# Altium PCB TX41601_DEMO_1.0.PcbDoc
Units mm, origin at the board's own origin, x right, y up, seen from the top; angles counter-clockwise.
Board outline 65 x 65 mm, 4 copper layers (Top Layer, Signal Layer 1, Signal Layer 2, Bottom Layer), stack 0.778 mm thick; 65 components, 52 nets, 196 pads, 383 vias.
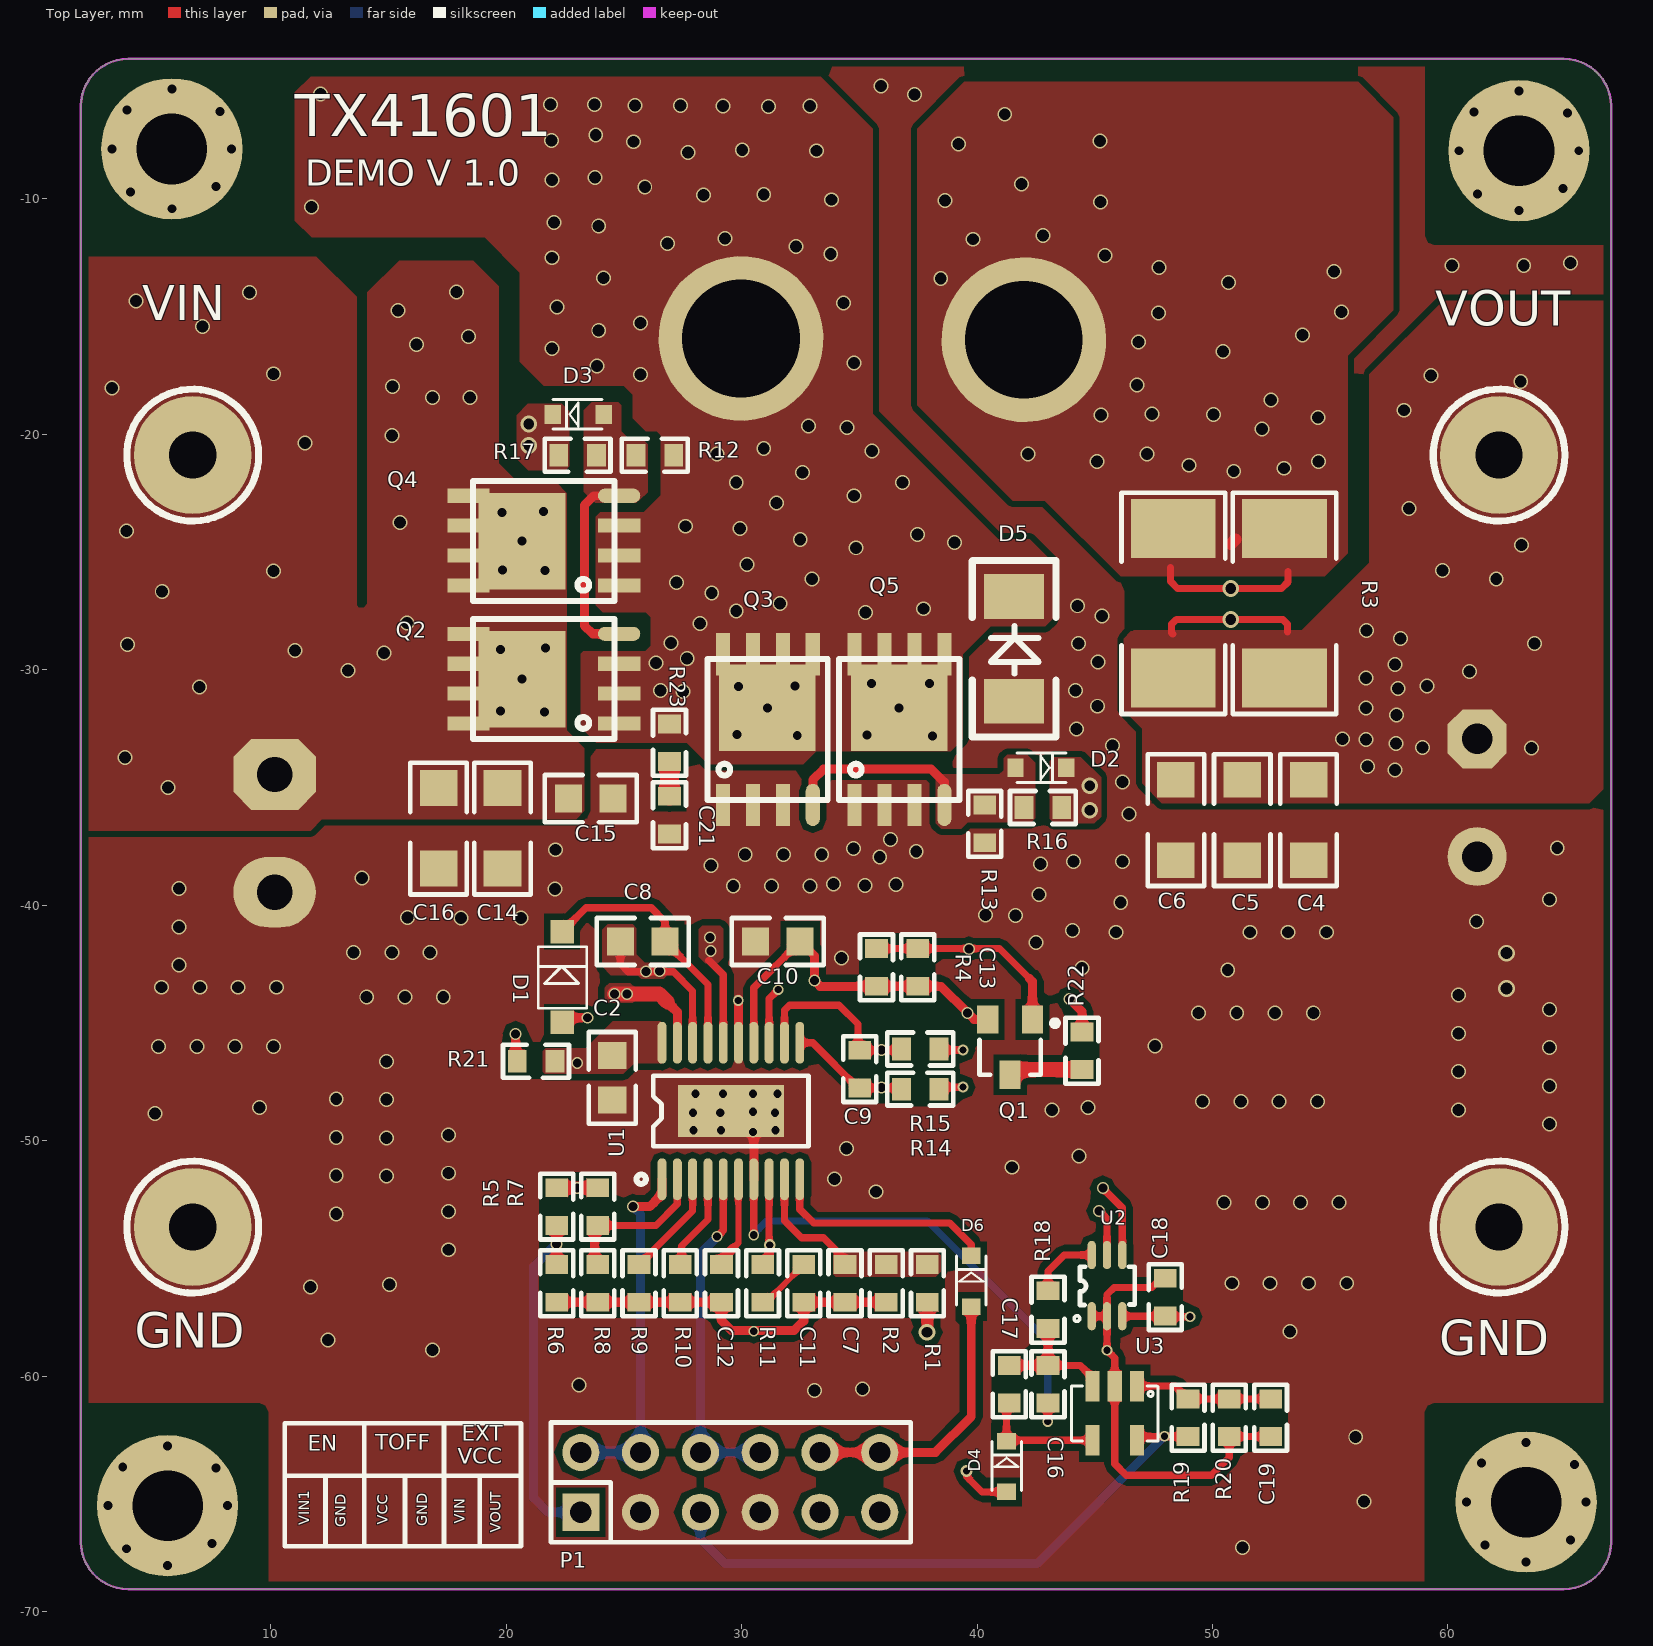
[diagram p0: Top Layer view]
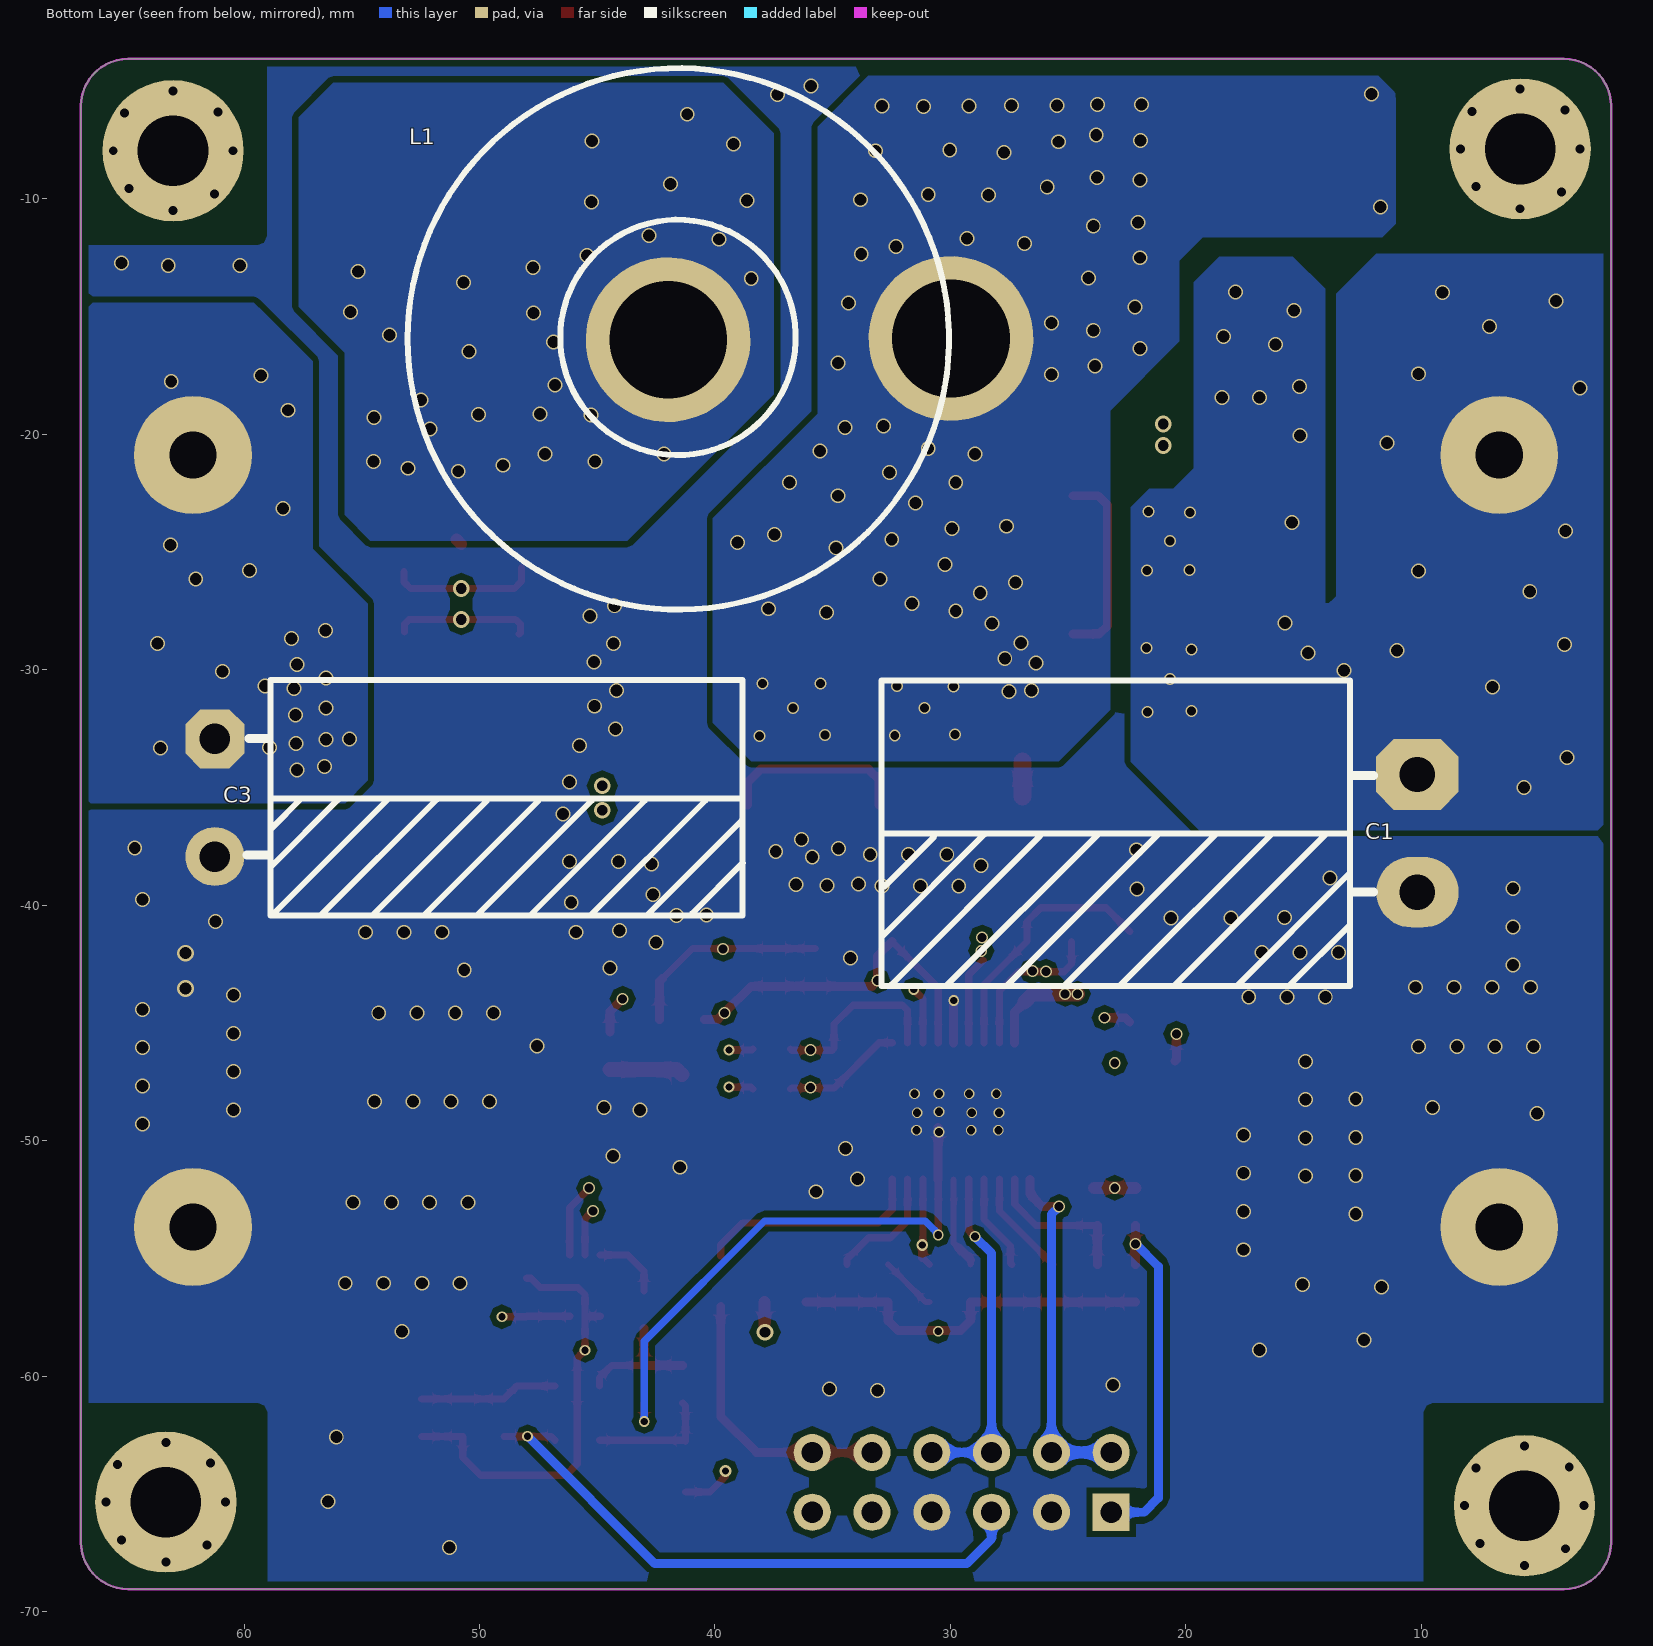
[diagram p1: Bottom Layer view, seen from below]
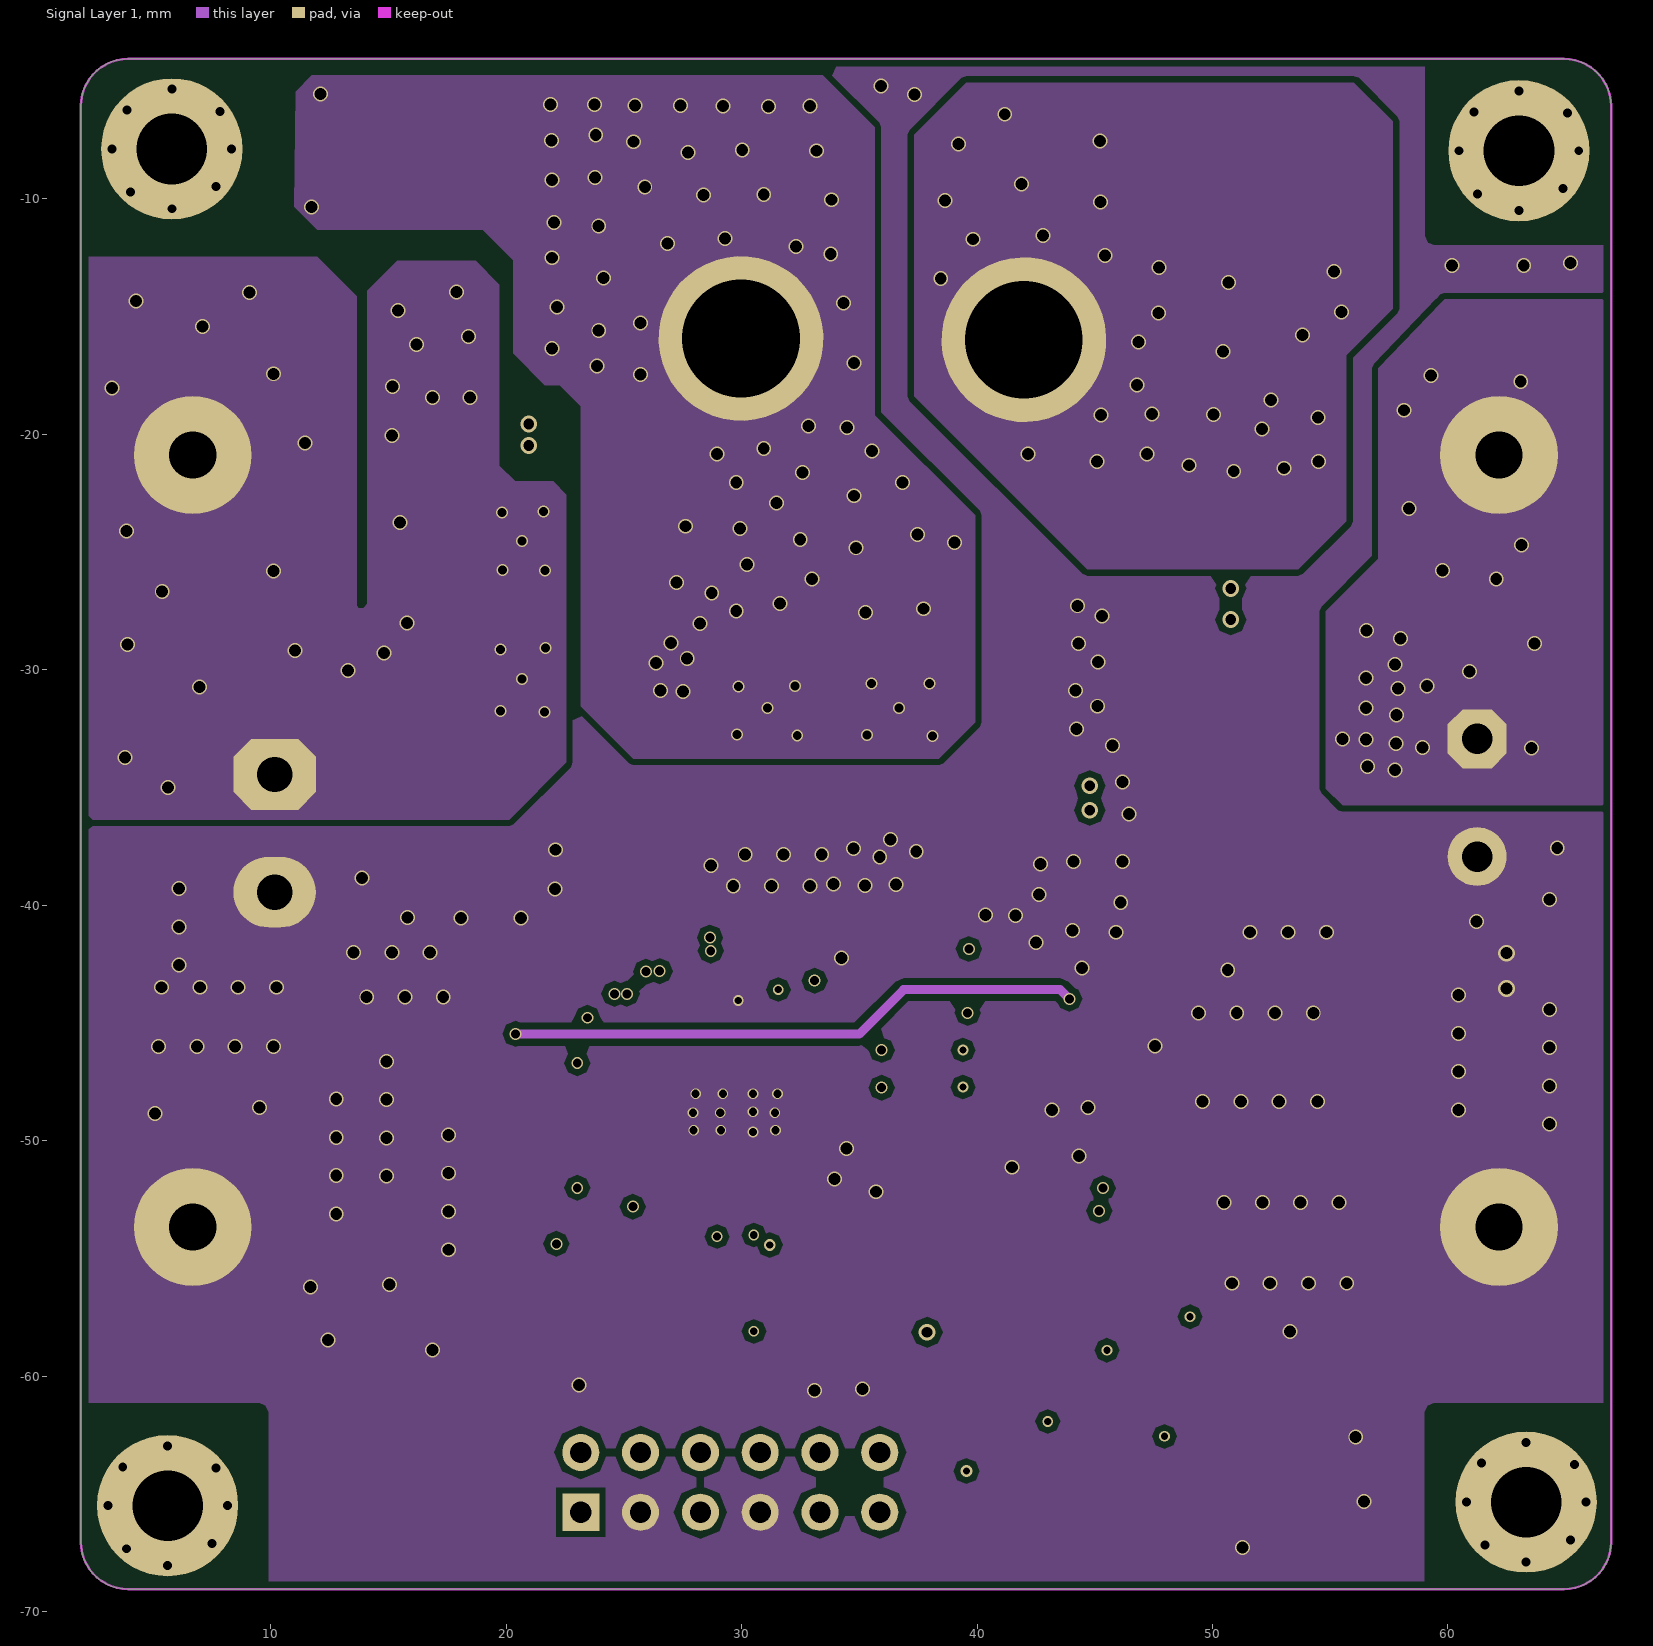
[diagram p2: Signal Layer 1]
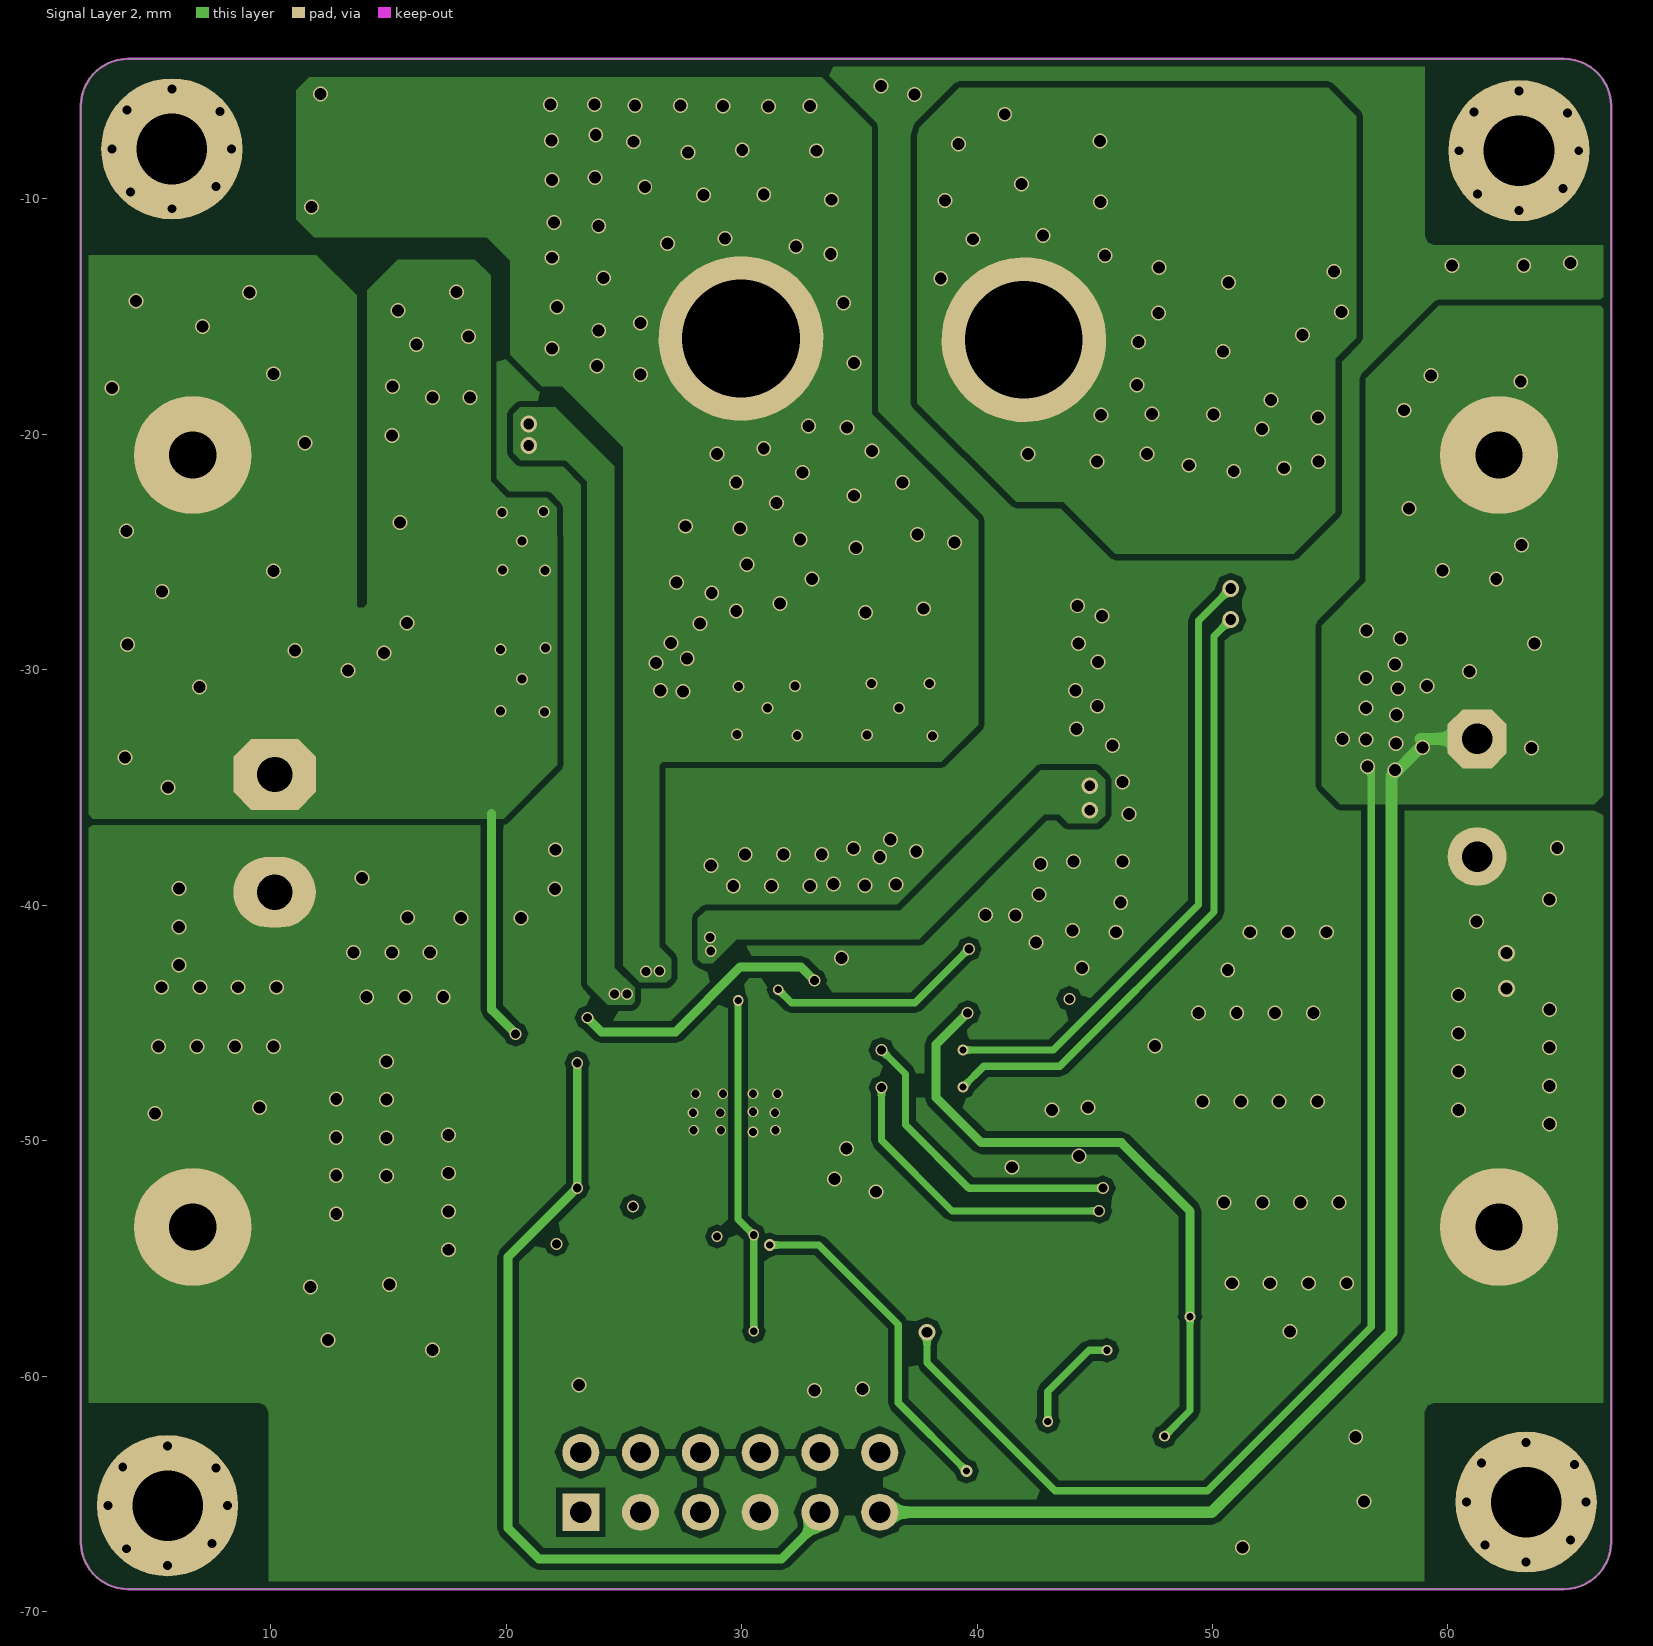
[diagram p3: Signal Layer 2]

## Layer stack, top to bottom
Top Layer: signal copper 0.0356
Dielectric: core 0.254, FR-4, Dk 4.2
Signal Layer 1: signal copper 0.036
Dielectric: prepreg 0.127, Dk 4.2
Signal Layer 2: signal copper 0.036
Dielectric: core 0.254, Dk 4.2
Bottom Layer: signal copper 0.0356

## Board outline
1.931,-67.05 ccw(c3.931,-67.05) 3.931,-69.05 64.931,-69.05 ccw(c64.931,-67.05) 66.931,-67.05 66.931,-6.05 ccw(c64.931,-6.05) 64.931,-4.05 3.931,-4.05 ccw(c3.931,-6.05) 1.931,-6.05

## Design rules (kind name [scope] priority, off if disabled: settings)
Clearance [All] p1: gap=0.254
PlaneConnect [All] p1: planeconnectstyle=Direct reliefexpansion=0.508 reliefentries=4 reliefconductorwidth=0.254 reliefairgap=0.254
PolygonConnect [All] p1: connectstyle=Direct reliefconductorwidth=0.254 reliefentries=4 polygonreliefangle="90 Angle" airgapwidth=0.254
RoutingVias [All] p1: holewidth=0.711 width=1.27 viastyle="Through Hole" minholewidth=0.711 minwidth=1.27 maxholewidth=0.711 maxwidth=1.27
SilkscreenOverComponentPads SilkToSolderMaskClearance [IsPad] p1: minsilkscreentomaskgap=0.254
SolderMaskExpansion [All] p1: expansion=0.102
Width [All] p1: maxlimit=2.54 minlimit=0.127 preferedwidth=0.381
26 further rules are at their usual default settings.

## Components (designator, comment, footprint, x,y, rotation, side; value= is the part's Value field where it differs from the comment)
C1 "Comment" C13*21 11.887,-36.957 r270 bottom locked
C2 "100nF/100V" 0805 24.74,-47.295 r90 top
C3 "Comment" C10*20 58.826,-37.871 r90 bottom locked
C4 "22uF/25V" 1206 53.95,-36.398 r180 top
C5 "22uF/25V" 1206 51.13,-36.398 r180 top (schematic designator C6)
C6 "22uF/25V" 1206 48.311,-36.398 r180 top (schematic designator C7)
C7 "47pF/25V" 0603 34.524,-55.939 r270 top (schematic designator C9)
C8 "100nF/100V" 0805 25.832,-41.784 r0 top (schematic designator C2)
C9 "1nF/25V" 0603 35.154,-46.838 r270 top
C10 "10uF/16v" 0805 31.496,-41.3 r180 top (schematic designator C2)
C11 "3.3nF/25v" 0603 32.502,-56.185 r90 top
C12 "100nF/50V" 0603 29.275,-55.939 r270 top
C13 "1nF/25V" 0603 37.617,-42.52 r270 top
C14 "2.2uF/100V" 1206 19.71,-36.754 r180 top (schematic designator C6)
C15 "100nF/100V" 0805 23.622,-35.712 r0 top (schematic designator C16)
C16 "NC" 0603 43.147,-60.223 r270 top (schematic designator C9)
C16 "2.2uF/100V" 1206 16.993,-36.754 r180 top (schematic designator C6)
C17 "NC" 0603 41.504,-60.223 r270 top (schematic designator C9)
C18 "NC" 0603 47.854,-56.769 r90 top (schematic designator C9)
C19 "NC" 0603 52.603,-61.646 r270 top (schematic designator C9)
C21 "NC" 0603 26.797,-36.297 r90 top (schematic designator C9)
D1 "SD44148" SOD123 22.352,-42.596 r90 top (schematic designator LED)
D2 "NC" SS14 42.901,-34.29 r0 top
D3 "1N4148WS" SS14 22.86,-19.025 r180 top
D4 "NC" SS14 41.378,-63.652 r90 top
D5 "NC" M7 41.58,-26.873 r90 top (schematic designator D17)
D6 "1N4148WS" SS14 39.878,-55.778 r90 top
L1 "L-D12" L-D12 41.605,-15.926 r220 bottom
P1 "" DIP16-2.54 32.055,-64.516 r0 top
Q1 "AO3442" SOT23-3 41.402,-46.025 r180 top
Q2 "TX106085" "MOS 5*6" 18.593,-27.838 r270 top
Q3 "TX106085" "MOS 5*6" 33.655,-29.54 r180 top
Q4 "TX106085" "MOS 5*6" 18.593,-21.971 r270 top
Q5 "TX106085" "MOS 5*6" 39.243,-29.54 r180 top
R1 "270K/1%" 0603 38.024,-55.939 r270 top
R2 "30K/1%" 0603 36.274,-55.939 r270 top
R3 "8mR" 2512 53.061,-27.178 r90 top
R4 "10K" 0603 35.865,-42.52 r270 top (schematic designator R9)
R5 "100K" 0603 22.276,-52.68 r270 top
R6 "10K" 0603 22.276,-55.939 r270 top
R7 "1M" 0603 24.026,-52.68 r270 top
R8 "10K" 0603 24.026,-55.939 r270 top
R9 "24K" 0603 25.503,-56.185 r90 top
R10 "120K" 0603 27.253,-56.185 r90 top
R11 "10K" 0603 30.753,-56.185 r90 top
R12 "10K" 0603 26.187,-20.752 r0 top (schematic designator R9)
R13 "10K" 0603 40.462,-36.424 r270 top (schematic designator R9)
R14 "10R" 0603 37.465,-47.676 r0 top (schematic designator R10)
R15 "10R" 0603 37.465,-45.969 r0 top (schematic designator R10)
R16 "4.7R" 0603 42.672,-35.711 r0 top (schematic designator R9)
R17 "4.7R" 0603 22.905,-20.752 r0 top (schematic designator R9)
R18 "NC" 0603 42.875,-57.302 r90 top (schematic designator R1)
R19 "NC" 0603 49.098,-61.646 r270 top (schematic designator R1)
R20 "NC" 0603 50.571,-61.892 r90 top (schematic designator R1)
R21 "10R" 0603 21.387,-46.761 r180 top (schematic designator R9)
R22 "10R" 0603 44.323,-46.304 r90 top (schematic designator R9)
R23 "NC" 0603 26.797,-33.223 r90 top (schematic designator R10)
U1 "TX41601" TSSOP-20P 29.54,-48.743 r90 top locked
U2 "NC" SOT363 45.517,-56.159 r180 top
U3 "NC" SOT23-6L 46.787,-62.763 r180 top (schematic designator U9)
? "" gudingkong 5.791,-7.874 r0 top locked
? "" gudingkong 5.613,-65.507 r0 top locked
? "" gudingkong 63.322,-65.354 r0 top locked
? "" gudingkong 63.017,-7.95 r0 top locked
? "NC" 2512 48.336,-27.178 r90 top

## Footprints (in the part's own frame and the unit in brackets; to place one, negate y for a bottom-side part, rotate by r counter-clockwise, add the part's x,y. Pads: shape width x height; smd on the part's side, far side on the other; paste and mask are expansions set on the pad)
0603 [mm]
  rect 0.8x0.965 smd: 1(0.923,-0.136) 2(-0.677,-0.136)
  silkscreen extent -1.28,-0.84 1.52,0.56
0805 [mm]
  rect 1.14x1.2 smd: 1(-0.986,0.242) 2(0.914,0.242)
  silkscreen extent -1.99,-0.76 1.91,1.24
1206 [mm]
  rect 1.6x1.52 smd: 1(-0.132,1.688) 2(-0.132,-1.732)
  silkscreen extent -1.33,-2.81 1.07,2.79
2512 [mm] "ÌùÆ¬Ô"
  rect 2.5x3.6 smd: 1(-3.175,0) 2(3.175,0)
  silkscreen extent -4.7,-2.2 4.7,2.2, body extent -3.17,-1.65 3.17,1.65, height 1.2
C10*20 [mm]
  oct 2.5x2.5 hole 1.3: 1(4.938,2.413)
  round 2.5 hole 1.3: 2(-0.062,2.413)
  silkscreen extent -2.57,-20.02 7.44,1.04
C13*21 [mm]
  oct 3x3.5 hole 1.5: 1(-2.512,1.728)
  oval 3x3.5 hole 1.5: 2(2.488,1.728)
  silkscreen extent -6.5,-21.03 6.48,-0.13
DIP16-2.54 [mil]
  rect 62x62 hole 35.43: 1(-350,-50)
  round 62 hole 35.43: 2(-350,50) 3(-250,-50) 4(-250,50) 5(-150,-50) 6(-150,50) 7(-50,-50) 8(-50,50) 9(50,-50) 10(50,50) 11(150,-50) 12(150,50)
  silkscreen extent -400,-100 202,100
gudingkong [mm]
  round 6 hole 3: 0(0,0)
L-D12 [mm]
  round 7 hole 5: 1(-0.259,-0.284) 2(8.912,7.478)
  silkscreen extent -11.45,-11.48 11.55,11.52
M7 [mm]
  rect 1.905x2.54 smd: 1(-4.463,0.007) 2(-0.018,0.007)
  silkscreen extent -5.99,-1.77 1.51,1.79
"MOS 5*6" [mm]
  rect 4.1x3.68 smd: 0(2.56,2.075)
  rect 0.6x1.8 smd: 1(4.445,6.2) 2(3.175,6.2) 3(1.905,6.2) 5(0.635,-0.2) 6(1.905,-0.2) 7(3.175,-0.2) 8(4.445,-0.2)
  oval 0.6x1.8 smd: 4(0.635,6.2)
  silkscreen extent 0,0 5.1,6
SOD123 [mm]
  rect 1x1 smd: 1(-2.375,-0.025) 2(1.475,-0.025)
  silkscreen extent -1.78,-1.07 0.82,1
SOT23-3 [mm]
  rect 0.9x1.2 smd: 1(-0.95,-1.175) 2(0.95,-1.175) 3(0,1.175)
  silkscreen extent -2.03,-1.14 1.3,1.18, body extent -1.45,-1.4 1.45,1.4, height 1.2
SOT23-6L [mm]
  rect 0.6x1.3 smd: 1(-0.01,-2.337) 2(0.94,-2.337) 3(1.89,-2.337) 4(1.89,-0.037) 6(-0.01,-0.037)
  silkscreen extent -0.89,-2.34 2.77,0
SOT363 [mm]
  oval 0.35x1.2 smd: 1(0.65,1.3) 2(0,1.3) 3(-0.65,1.3) 4(-0.65,-1.3) 5(0,-1.3) 6(0.65,-1.3)
  silkscreen extent -1.17,-0.8 1.39,1.52
SS14 [mm]
  rect 0.7x0.8 smd: 1(-1.27,0.127) 2(0.88,0.127)
  silkscreen extent -1.21,-0.5 0.88,0.75
TSSOP-20P [mm] "TSOP, 20-Leads, Body 6.5x4.4mm, Pitch 0.65mm, IPC Low Density"
  oval 1.78x0.38 smd: 1(-2.9,2.925) 2(-2.9,2.275) 3(-2.9,1.625) 4(-2.9,0.975) 5(-2.9,0.325) 6(-2.9,-0.325) 7(-2.9,-0.975) 8(-2.9,-1.625) 9(-2.9,-2.275) 10(-2.9,-2.925) 11(2.9,-2.925) 12(2.9,-2.275) 13(2.9,-1.625) 14(2.9,-0.975) 15(2.9,-0.325) 16(2.9,0.325) 17(2.9,0.975) 18(2.9,1.625) 19(2.9,2.275) 20(2.9,2.925)
  rect 2.2x4.5 smd: 21(0,0)
  silkscreen extent -3.1,-3.3 1.5,4.01

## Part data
C1 D2 D3 Q1 Q2 Q3 Q4 Q5 R3 ?: "TX41601"
C2 C4 C5 C6 C7 C8 C9 C10 C11 C12 C13 C14 C15 C16 C16 C17 C18 C19 C21: library part "Cap Semi", "Capacitor (Semiconductor SIM Model)"
D1: library part LED0, "Typical INFRARED GaAs LED"
D5: library part DIODE, "Diode"
R1 R2 R4 R5 R6 R7 R8 R9 R10 R11 R14 R15 R18 R19 R20 R21 R22 R23: library part "Res Semi", "Semiconductor Resistor"
R12 R13 R16 R17: library part "Res Semi", "TX41601"
U3: library part USBLC6-2SC6

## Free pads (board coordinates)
  round 2 on Mech13: 7(18.074,-60.325)
  round 5 hole 2: ""(6.68,-53.67) ""(6.68,-20.879) ""(62.173,-53.67) ""(62.173,-20.879)

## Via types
v1: diameter 0.635, hole 0.508, Top Layer to Bottom Layer, 277 vias
v2: diameter 0.508, hole 0.381, Top Layer to Bottom Layer, 40 vias
v3: diameter 0.762, hole 0.381, Top Layer to Bottom Layer, 32 vias
v4: diameter 0.45, hole 0.35, Top Layer to Bottom Layer, 12 vias
v5: diameter 0.457, hole 0.305, Top Layer to Bottom Layer, 8 vias
v6: diameter 0.711, hole 0.457, Top Layer to Bottom Layer, 7 vias
v7: diameter 0.457, hole 0.33, Top Layer to Bottom Layer, 3 vias
v8: diameter 0.711, hole 0.508, Top Layer to Bottom Layer, 2 vias
v9: diameter 0.508, hole 0.305, Top Layer to Bottom Layer, 2 vias

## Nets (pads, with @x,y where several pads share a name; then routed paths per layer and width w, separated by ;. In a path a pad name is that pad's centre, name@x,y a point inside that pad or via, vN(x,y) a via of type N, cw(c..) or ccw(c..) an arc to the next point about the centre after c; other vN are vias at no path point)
1: 
8: 
23: 
+IN: C19.2 R19.2 R20.1 U3.1 | length 5.9
  Top Layer w0.305: U3.1 48.42,-60.427 R19.2 R20.1 C19.2
-IN: C16.2@43.011,-59.546 C17.2 R18.2 U3.3 | length 5.7
  Top Layer w0.305: C16.2@43.011,-59.546 44.383,-59.546 44.897,-60.061 U3.3
  Top Layer w0.381: C17.2 43.011,-59.546 R18.2
AGND: C7.1 C11.2 C12.1 C16.1@43.011,-61.146 C18.1 C19.1 R2.1 R6.1 R8.1 R9.2 R10.2 R20.2 U1.7 U2.1 U2.2 U3.2 | length 75
  Top Layer w0.305: v7(30.515,-54.01) U1.7 ; v5(43.002,-61.925) 43.002,-61.155 C16.1@43.011,-61.146 ; U2.1 U2.2 ; C18.1 47.811,-55.846 47.422,-56.236 45.822,-56.236 45.517,-56.54 U2.2 ; C19.1 R20.2 50.707,-63.466 49.962,-64.211 46.33,-64.211 45.847,-63.729 U3.2 45.847,-59.233 v5(45.517,-58.903) U2.2
  Top Layer w0.381: R6.1 R8.1 R9.2 R10.2 C12.1 29.139,-57.638 29.566,-58.064 32.233,-58.064 32.638,-57.659 C11.2 C7.1 R2.1
  Signal Layer 2 w0.305: 29.855,-44.044 29.849,-44.05 29.849,-53.344 v7(30.515,-54.01) v7(30.515,-58.1) ; v5(43.002,-61.925) 43.002,-60.655 44.755,-58.903 v5(45.517,-58.903)
  Bottom Layer w0.305: v7(30.515,-54.01) 30.515,-53.965 31.064,-53.416 37.897,-53.416 43.002,-58.522 v5(43.002,-61.925)
BG: D2.2 R16.1 U1.16 | length 3.8
  Top Layer w0.305: 28.6,-42.342 29.215,-42.957 U1.16
  other v2: 28.685,-41.935 28.651,-41.377
  other v6: 44.78,-35.966 44.78,-34.925
BG2: D2.1 Q3.4 Q5.4 R13.2 R16.2 | length 8
  Top Layer w0.381: Q3.4 33.02,-34.671 33.477,-34.214 38.049,-34.214 38.608,-34.773 Q5.4
BST: 
C9: 
C17-3: 
EN: P1.2 P1.4 U1.1 | length 15.2
  Top Layer w0.381: v2(25.375,-52.807) 26.086,-52.807 26.615,-52.277 U1.1
  Bottom Layer w0.381: v2(25.375,-52.807) 25.705,-53.137 P1.4
  Bottom Layer w0.508: P1.2 P1.4
EXTVCC: D6.1 P1.10 P1.12 | length 11.7
  Top Layer w0.381: P1.10 P1.12 38.227,-63.246 39.751,-61.722 D6.1
INTVCC: 
ISNS1: C9.2 R15.2 U1.12 U2.4 | length 24.1
  Top Layer w0.305: U1.12 31.815,-44.461 32.029,-44.247 34.138,-44.247 34.941,-45.051 34.941,-46.084 C9.2 36.729,-46.161 36.731,-46.162 R15.2 ; v2(45.339,-52.019) 46.167,-52.847 U2.4
  Signal Layer 2 w0.305: v2(35.941,-46.152) 36.957,-47.168 36.957,-49.327 39.649,-52.019 v2(45.339,-52.019)
ISNS2: C9.1 R14.2 U1.11 U2.5 | length 19.9
  Top Layer w0.305: U1.11 33.016,-45.843 34.934,-47.761 C9.1 36.737,-47.761 R14.2 ; v2(45.187,-52.984) 45.517,-53.314 U2.5
  Signal Layer 2 w0.305: v2(35.941,-47.752) 35.941,-49.987 38.938,-52.984 v2(45.187,-52.984)
NDRV: C13.2 Q1.1 R4.2 U1.13 | length 20.5
  Top Layer w0.305: U1.13 31.165,-43.976 v5(31.555,-43.586) ; R4.2 C13.2 40.954,-41.843 42.224,-43.112
  Top Layer w0.381: 42.224,-43.112 42.352,-43.241 Q1.1
  Signal Layer 2 w0.305: v5(31.555,-43.586) 32.114,-44.145 37.363,-44.145 v2(39.649,-41.859)
NetC1_1: C1.1 C14.2 C15.1 C16.2@17.125,-35.022 pad.@6.68,-20.879 Q2.0 Q2.5 Q2.6 Q2.7 Q2.8 Q4.0 Q4.5 Q4.6 Q4.7 Q4.8 R21.1 R22.1 | length 37.1
  Top Layer w0.381: v2(20.396,-45.466) 20.396,-46.558 R21.1 ; v2(43.917,-43.976) 44.459,-44.518 R22.1
  Signal Layer 1 w0.381: v2(20.396,-45.466) 20.409,-45.479 34.988,-45.479 36.881,-43.586 43.527,-43.586 v2(43.917,-43.976)
  Signal Layer 2 w0.381: 19.38,-36.093 19.38,-44.45 v2(20.396,-45.466)
  other v1: 5.639,-35.001 3.81,-33.731 6.96,-30.734 13.284,-30.023 14.808,-29.286 11.024,-29.185 3.912,-28.931 15.773,-28.016 5.385,-26.67 10.109,-25.806 3.861,-24.105 15.494,-23.749 11.455,-20.371 15.138,-20.041 16.866,-18.44 18.466,-18.44 3.251,-18.034 15.164,-17.958 10.109,-17.424 16.18,-16.18 18.393,-15.85 7.087,-15.418 15.405,-14.732 4.267,-14.326 9.093,-13.97 17.882,-13.945
  other v2: 21.615,-31.801 19.761,-31.75 20.668,-30.398 19.761,-29.134 21.666,-29.083 21.641,-25.781 19.837,-25.756 20.668,-24.531 19.812,-23.317 21.59,-23.266
NetC8_1: C8.2 D1.2 U1.17 | length 10.9
  Top Layer w0.305: D1.2 23.391,-40.107 26.162,-40.107 26.746,-40.69 C8.2 28.565,-43.362 U1.17
NetC8_2: C8.1 D5.2 L1.2 Q2.1 Q2.2 Q2.3 Q3.0 Q3.5 Q3.6 Q3.7 Q3.8 Q4.1 Q4.2 Q4.3 Q5.0 Q5.5 Q5.6 Q5.7 Q5.8 R12.1 R23.1 U1.18 | length 6.7
  Top Layer w0.305: C8.1 24.846,-42.499 25.171,-42.824 v2(25.933,-42.824) 27.102,-42.824 27.915,-43.638 U1.18
  other v1: 27.508,-30.912 26.543,-30.886 26.365,-29.718 27.686,-29.515 27,-28.854 28.219,-28.042 35.255,-27.559 29.769,-27.508 37.719,-27.407 31.623,-27.178 28.727,-26.746 27.229,-26.289 32.995,-26.137 30.226,-25.527 34.849,-24.816 39.04,-24.587 32.487,-24.46 37.465,-24.257 29.921,-24.003 27.61,-23.901 31.471,-22.911 34.773,-22.606 29.769,-22.047 36.83,-22.047 32.588,-21.615 28.956,-20.828 35.535,-20.701 30.937,-20.599 34.468,-19.71 32.842,-19.634 25.705,-17.45 23.851,-17.094 34.773,-16.967 21.946,-16.358 23.927,-15.596 25.705,-15.265 22.149,-14.58 34.315,-14.427 24.13,-13.36 21.946,-12.497 33.782,-12.344 32.309,-12.014 26.848,-11.887 29.286,-11.684 23.927,-11.151 22.022,-10.998 11.735,-10.338 33.807,-10.033 28.372,-9.83 30.937,-9.804 25.883,-9.5 21.946,-9.195 23.774,-9.093 27.711,-8.026 33.172,-7.95 30.023,-7.925 25.4,-7.569 21.92,-7.518 23.8,-7.29 31.14,-6.071 29.202,-6.045 32.893,-6.045 25.476,-6.02 27.407,-6.02 21.869,-5.994 23.749,-5.994 12.116,-5.537
  other v2: 26.518,-42.799 38.1,-32.817 32.36,-32.791 35.331,-32.766 29.794,-32.741 31.095,-31.615 36.683,-31.615 29.87,-30.709 32.258,-30.683 35.509,-30.582 37.973,-30.582
NetC9_2: ?.2 L1.1 R3.2 R15.1 | length 34.1
  Top Layer w0.305: R15.1 38.435,-46.152 v5(39.395,-46.152) ; 48.209,-25.654 48.209,-26.238 48.514,-26.543 v6(50.775,-26.543) 52.934,-26.543 53.213,-26.264 53.213,-25.832
  Top Layer w0.508: 50.775,-24.663 50.978,-24.46
  Signal Layer 2 w0.305: v5(39.395,-46.152) 43.231,-46.152 49.403,-39.98 49.403,-27.915 v6(50.775,-26.543)
  other v1: 50.902,-21.565 53.035,-21.438 48.997,-21.311 45.085,-21.158 54.508,-21.158 42.164,-20.828 47.219,-20.828 52.095,-19.761 54.483,-19.279 45.263,-19.177 50.038,-19.152 47.422,-19.126 52.476,-18.542 46.787,-17.907 50.444,-16.485 46.863,-16.078 53.823,-15.773 47.701,-14.834 55.474,-14.808 50.673,-13.538 38.456,-13.386 55.169,-13.081 47.727,-12.903 45.441,-12.395 39.827,-11.709 42.799,-11.557 45.237,-10.135 38.633,-10.058 41.885,-9.373 39.218,-7.671 45.212,-7.544 41.173,-6.401
NetC11_1: C11.1 R11.2 | length 2.4
  Top Layer w0.254: R11.2 31.038,-56.862 C11.1
NetC12_2: C12.2 U1.6 | length 3.9
  Top Layer w0.254: C12.2 C12.2@29.139,-55.062 ; 29.642,-54.559 29.855,-54.346 29.855,-53.147 29.855,-51.653 U1.6
  Top Layer w0.381: C12.2@29.139,-55.062 29.642,-54.559
NetC17_1: D6.2 U1.10 | length 9.7
  Top Layer w0.305: U1.10 32.465,-52.912 33.045,-53.492 38.83,-53.492 39.751,-54.413 D6.2
NetL1_1: 
NetP1_3: P1.1 R5.1 R6.2 | length 15.1
  Top Layer w0.381: R6.2 R5.1
  Bottom Layer w0.381: v2(22.123,-54.381) 21.158,-55.347 21.158,-65.176 21.768,-65.786 P1.1
NetQ2_2: 
NetQ3_2: 
NetR1_2: C7.2 R1.2 R2.2 U1.9 | length 5.2
  Top Layer w0.305: U1.9 31.815,-53.405 32.537,-54.127 33.477,-54.127 34.388,-55.038 C7.2
NetR7_1: R7.1 R8.2 U1.2 | length 6.5
  Top Layer w0.305: R7.1 26.357,-53.603 27.265,-52.694 U1.2
  Top Layer w0.381: R8.2@23.753,-55.262 R7.1@23.753,-53.603
NetR9_1: R9.1 U1.3 | length 4.6
  Top Layer w0.305: R9.1 25.639,-55.26 27.915,-52.984 U1.3
NetR10_1: R10.1 U1.4 | length 4.1
  Top Layer w0.305: R10.1 27.445,-55.206 27.445,-54.47 28.565,-53.35 U1.4
NetR11_1: D4.1 R11.1 U1.8 | length 20.8
  Top Layer w0.305: R11.1 R11.1@31.165,-54.985 ; U1.8 R11.1@31.165,-54.985 ; R11.1@31.191,-54.959 R11.1@31.165,-54.985 ; v9(39.548,-64.033) 39.548,-64.262 40.208,-64.922 D4.1
  Top Layer w0.381: R11.1@31.191,-54.959 v9(31.191,-54.432)
  Signal Layer 2 w0.305: v9(31.191,-54.432) 33.274,-54.432 36.652,-57.81 36.652,-61.138 v9(39.548,-64.033)
NewNet: 
NewNetC17-2: 
OUT: C17.1 D4.2 U3.4 | length 5.3
  Top Layer w0.305: C17.1 41.251,-61.263 D4.2 41.297,-62.727 U3.4
OUT2: R18.1 U2.6 | length 3
  Top Layer w0.305: R18.1 43.011,-55.55 43.702,-54.859 U2.6
PGND: C1.2 C2.1 C3.2 C4.1 C5.1 C6.1 C10.2 C14.1 C15.2 C16.1@17.125,-38.442 C21.2 D5.1 P1.3 P1.7 pad.@6.68,-53.67 pad.@62.173,-53.67 Q3.1 Q3.2 Q3.3 Q5.1 Q5.2 Q5.3 R13.1 U1.15 U1.21 | length 4.1
  Top Layer w0.381: U1.15 v5@29.865,-43.976 ; 30.515,-51.643 U1.21@30.515,-49.444
  other v1: 51.283,-67.285 56.439,-65.329 56.083,-62.586 33.096,-60.604 35.141,-60.554 23.089,-60.376 16.866,-58.903 12.421,-58.471 53.289,-58.115 11.684,-56.21 15.037,-56.109 50.825,-56.058 52.451,-56.058 54.077,-56.058 55.702,-56.058 17.551,-54.635 12.776,-53.111 17.551,-53.01 50.495,-52.629 52.121,-52.629 53.746,-52.629 55.372,-52.629 35.712,-52.172 33.934,-51.638 14.91,-51.511 12.776,-51.486 17.551,-51.384 41.478,-51.13 44.323,-50.648 34.442,-50.343 14.91,-49.886 12.776,-49.86 17.551,-49.759 64.313,-49.301 5.08,-48.844 43.18,-48.692 60.452,-48.692 9.525,-48.59 44.704,-48.59 49.581,-48.336 51.206,-48.336 52.832,-48.336 54.458,-48.336 14.91,-48.26 12.776,-48.235 64.313,-47.676 60.452,-47.066 14.91,-46.634 64.313,-46.05 5.232,-45.999 6.858,-45.999 8.484,-45.999 10.109,-45.999 47.549,-45.974 60.452,-45.441 49.403,-44.577 51.029,-44.577 52.654,-44.577 54.28,-44.577 64.313,-44.425 14.072,-43.891 15.697,-43.891 17.323,-43.891 60.452,-43.815 5.359,-43.485 6.985,-43.485 8.611,-43.485 10.236,-43.485 50.648,-42.748 44.45,-42.672 6.096,-42.545 34.239,-42.235 13.513,-42.012 15.138,-42.012 16.764,-42.012 42.494,-41.58 45.898,-41.148 51.587,-41.148 53.213,-41.148 54.839,-41.148 44.044,-41.072 6.096,-40.919 61.214,-40.691 18.085,-40.538 20.625,-40.538 15.799,-40.513 41.631,-40.437 40.361,-40.411 46.101,-39.878 64.313,-39.751 42.621,-39.548 22.073,-39.319 6.096,-39.294 29.642,-39.192 31.267,-39.192 32.893,-39.192 35.23,-39.167 36.551,-39.116 33.909,-39.091 13.868,-38.837 28.702,-38.303 42.697,-38.252 44.094,-38.151 46.167,-38.151 35.865,-37.948 30.15,-37.846 31.775,-37.846 33.401,-37.846 37.414,-37.719 22.098,-37.643 34.747,-37.592 64.643,-37.567 36.322,-37.211 46.457,-36.119 46.177,-34.773 45.745,-33.223 44.221,-32.512 45.117,-31.547 44.171,-30.886 45.136,-29.667 44.298,-28.88 45.314,-27.711 44.272,-27.28 60.173,-12.827 63.221,-12.827 65.202,-12.725 37.338,-5.563 35.916,-5.207
  other v4: 30.48,-49.632 27.957,-49.555 29.117,-49.555 31.437,-49.555 27.932,-48.819 29.091,-48.819 31.411,-48.819 30.48,-48.768 28.042,-48.006 29.202,-48.006 30.48,-48.006 31.521,-48.006
  other v5: 29.855,-44.044
  other v8: 62.484,-43.536 62.484,-42.037
Q4-3: 
RC: C21.1 R23.2 | length 1.5
  Top Layer w0.762: C21.1 R23.2
TG: D3.2 R17.2 U1.19 | length 4.3
  Top Layer w0.381: 26.822,-44.094 27.265,-44.537 U1.19
  Top Layer w0.635: v2(24.587,-43.764) 26.492,-43.764 26.822,-44.094
  other v2: 25.121,-43.764
  other v6: 20.955,-20.472 20.955,-19.558
TG1: D3.1 Q2.4 Q4.4 R12.2 R17.1 | length 8.4
  Top Layer w0.381: Q2.4 23.673,-28.473 23.317,-28.118 23.317,-23.012 23.724,-22.606 Q4.4
TG2: 
TOFF: 
TOFF1: P1.6 P1.8 U1.5 | length 14.5
  Top Layer w0.305: v7(28.956,-54.077) 29.215,-53.817 U1.5
  Bottom Layer w0.381: v7(28.956,-54.077) 28.245,-54.788 P1.6 P1.8
VCC: C10.1 C13.1 C18.2 D1.1 P1.5 Q1.2 R4.1 R19.1 U1.14 U2.3 U3.6 | length 83.1
  Top Layer w0.305: U1.14 30.515,-43.509 C10.1 ; U2.3 47.976,-57.459 47.997,-57.48 v5(49.047,-57.48) ; U3.6 46.955,-62.569 R19.1
  Top Layer w0.381: D1.1 22.568,-44.78 v2(23.444,-44.78) ; C10.1 33.096,-42.157 v2(33.096,-43.205) 33.333,-43.443 R4.1 C13.1 38.464,-43.443 v2(39.599,-44.577) 39.871,-44.85 Q1.2
  Signal Layer 2 w0.305: v5(47.955,-62.56) 49.047,-61.468 v5(49.047,-57.48)
  Signal Layer 2 w0.381: v2(23.444,-44.78) 24.054,-45.39 27.178,-45.39 29.947,-42.621 32.512,-42.621 v2(33.096,-43.205) ; v2(39.599,-44.577) 38.252,-45.923 38.252,-48.158 40.183,-50.089 46.126,-50.089 49.047,-53.01 v5(49.047,-57.48)
  Bottom Layer w0.381: P1.5 28.245,-66.904 29.312,-67.97 42.545,-67.97 v5(47.955,-62.56)
VCC1: 
VIN1: C2.2 P1.9 R5.2 R7.2 R21.2 U1.20 | length 37.5
  Top Layer w0.508: R5.2 v2(23.015,-52.003) R7.2
  Signal Layer 2 w0.381: v2(23.015,-46.708) v2(23.015,-52.003) 20.066,-54.951 20.066,-66.446 21.387,-67.767 31.699,-67.767 33.325,-66.142 P1.9
VIN2: Q1.3 R22.2 | length 3.1
  Top Layer w0.635: Q1.3 41.621,-46.981 R22.2
VOUT: ?.1 C3.1 C4.2 C5.2 C6.2 P1.11 pad.@62.173,-20.879 R1.1 R3.1 R14.1 | length 136.4
  Top Layer w0.305: R14.1 38.473,-47.727 v5(39.395,-47.727) ; 48.311,-28.473 48.26,-28.423 48.26,-28.067 48.463,-27.864 v6(50.775,-27.864) 52.984,-27.864 53.188,-28.067 53.188,-28.397
  Top Layer w0.508: v6(37.871,-58.141) 37.888,-58.124 R1.1
  Signal Layer 2 w0.305: v6(37.871,-58.141) 37.871,-59.436 43.307,-64.872 49.784,-64.872 56.744,-57.912 v1@56.744,-34.138 ; v5(39.395,-47.727) 40.284,-46.838 43.51,-46.838 50.063,-40.284 50.063,-28.575 v6(50.775,-27.864)
  Signal Layer 2 w0.508: P1.11 49.962,-65.786 57.607,-58.141 57.607,-34.519 v1@58.826,-33.299 ; 58.826,-32.933 C3.1
  other v1: 57.76,-34.265 56.591,-34.112 63.551,-33.325 58.928,-33.299 57.785,-33.122 56.515,-32.969 55.524,-32.944 57.81,-31.928 56.515,-31.623 57.887,-30.785 59.106,-30.683 56.515,-30.353 60.909,-30.074 57.76,-29.769 63.678,-28.88 57.988,-28.677 56.54,-28.334 62.052,-26.137 59.766,-25.781 63.119,-24.689 58.344,-23.139 58.141,-18.974 63.094,-17.755 59.284,-17.501
VOUT1: 
VOUT2: 
pads on no net: ?.0
copper on no net:
  other v3: 5.613,-68.047 63.322,-67.894 3.861,-67.335 61.57,-67.183 7.493,-67.107 65.202,-66.954 3.073,-65.507 8.153,-65.507 60.782,-65.354 65.862,-65.354 7.671,-63.906 3.708,-63.856 65.38,-63.754 61.417,-63.703 5.613,-62.967 63.322,-62.814 63.017,-10.49 5.791,-10.414 61.265,-9.779 4.039,-9.703 64.897,-9.55 7.671,-9.474 60.477,-7.95 65.557,-7.95 3.251,-7.874 8.331,-7.874 65.075,-6.35 61.112,-6.299 7.849,-6.274 3.886,-6.223 63.017,-5.41 5.791,-5.334

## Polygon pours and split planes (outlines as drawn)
NetR1_2 on Top Layer "Top Layer-NetR1_2" (solid, remove dead copper, pour order 456): 38.252,-55.778 33.985,-55.778 33.884,-55.677 33.884,-54.813 33.985,-54.712 38.303,-54.712 38.456,-54.864 38.456,-55.575
BG on Top Layer "gnd" (solid, remove dead copper, pour order 588): 28.321,-40.869 29.083,-40.869 29.215,-41.001 29.215,-42.235 28.981,-42.469 28.448,-42.469 28.169,-42.189 28.169,-41.021
TG on Top Layer "gnd" (solid, remove dead copper, pour order 602): 24.282,-43.409 24.384,-43.307 25.273,-43.307 25.451,-43.485 25.451,-44.069 25.375,-44.145 24.333,-44.145 24.181,-43.993 24.181,-43.497 24.27,-43.409
VIN1 on Top Layer "gnd" (solid, remove dead copper, pour order 610): 26.67,-46.507 26.619,-46.457 26.619,-45.009 26.543,-44.933 24.524,-44.933 23.381,-46.076 21.666,-46.076 21.539,-46.203 21.539,-47.066 21.641,-47.168 24.968,-47.168 25.425,-46.711 26.594,-46.711
NetC8_2 on Top Layer "gnd" (solid, remove dead copper, pour order 646): 26.797,-43.002 26.822,-42.977 26.822,-42.57 26.695,-42.443 25.883,-42.443 25.527,-42.088 25.527,-40.97 25.375,-40.818 24.301,-40.818 24.079,-41.04 24.079,-42.602 24.445,-42.968 25.58,-42.968 25.741,-43.129 26.679,-43.129 26.797,-43.011
TG1 on Top Layer "  " (solid, remove dead copper, pour order 664): 25.552,-22.885 25.527,-22.911 23.774,-22.911 23.292,-22.428 23.292,-18.974 23.622,-18.644 24.765,-18.644 24.892,-18.771 24.892,-19.863 25.273,-20.244 25.832,-20.244 26.01,-20.422 26.01,-22.454 25.679,-22.784
TG on Top Layer "  " (solid, remove dead copper, pour order 668): 20.917,-18.707 22.365,-18.707 22.682,-19.025 22.682,-21.361 22.53,-21.514 20.93,-21.514 20.447,-21.031 20.447,-19.177
BG2 on Top Layer "  " (solid, remove dead copper, pour order 670): 38.252,-34.671 38.478,-34.445 40.942,-34.445 41.123,-34.265 41.123,-33.757 41.275,-33.604 42.122,-33.604 42.469,-33.951 42.469,-36.297 42.291,-36.474 39.599,-36.474 39.319,-36.754 38.481,-36.754 38.252,-36.525 38.252,-36.271
BG on Top Layer "  " (solid, remove dead copper, pour order 672): 43.252,-33.706 44.399,-33.706 45.263,-34.569 45.263,-36.233 44.971,-36.525 43.282,-36.525 43.078,-36.322 43.078,-33.879
NetC1_1 on Top Layer "  " (solid, remove dead copper, pour order 680): 11.684,-36.83 1.956,-36.83 1.041,-35.916 1.041,-13.183 1.778,-12.446 11.938,-12.446 13.64,-14.148 13.64,-27.254 13.741,-27.356 13.945,-27.356 14.097,-27.203 14.097,-13.97 15.443,-12.624 18.593,-12.624 19.685,-13.716 19.685,-21.234 20.472,-22.022 22.098,-22.022 22.568,-22.492 22.568,-32.575 23.317,-33.325 23.317,-35.992 22.962,-36.347 12.167,-36.347
NetC8_2 on Top Layer "  " (solid, remove dead copper, pour order 688): 23.165,-29.312 23.165,-32.436 23.825,-33.096 27.661,-33.096 28.575,-34.011 32.614,-34.011 33.172,-33.452 38.887,-33.452 39.395,-32.944 39.395,-29.337 40.589,-28.143 42.901,-28.143 43.205,-27.838 43.205,-25.425 42.24,-24.46 40.894,-24.46 35.56,-19.126 35.56,-7.01 33.35,-4.801 11.684,-4.801 11.024,-5.461 11.024,-10.922 11.735,-11.633 19.075,-11.633 20.574,-13.132 20.574,-16.916 21.59,-17.932 24.994,-17.932 25.375,-18.313 25.375,-19.304 25.933,-19.863 26.391,-19.863 26.568,-20.041 26.568,-22.581 25.832,-23.317 23.991,-23.317 23.8,-23.509 23.8,-27.254 24.105,-27.559 25.933,-27.559 26.137,-27.762 26.137,-28.981 25.908,-29.21 23.266,-29.21
NetC9_2 on Top Layer "  " (solid, remove dead copper, pour order 696): 54.762,-26.035 46.101,-26.035 42.875,-22.809 41.504,-22.809 37.465,-18.771 37.465,-7.01 39.446,-5.029 56.185,-5.029 57.683,-6.528 57.683,-14.732 55.753,-16.662 55.753,-25.044
VOUT on Top Layer "  " (solid, remove dead copper, pour order 708): 46.634,-28.346 46.66,-28.321 53.797,-28.321 56.667,-25.451 56.667,-17.45 59.792,-14.326 66.853,-14.326 68.478,-15.951 68.478,-33.193 66.01,-35.662 47.854,-35.662 47.015,-34.823 47.015,-32.512 46.228,-31.725 46.228,-28.677 46.533,-28.372
PGND on Top Layer "  " (solid, remove dead copper, pour order 716): 0.584,-3.708 69.317,-3.708 69.317,-70.333 -0.229,-70.333 -0.229,-51.511
TG on Signal Layer 2 "  " (solid, remove dead copper, pour order 666): 25.324,-44.221 24.308,-44.221 23.444,-43.358 23.444,-22.022 22.53,-21.107 20.625,-21.107 20.295,-20.777 20.295,-19.152 20.599,-18.847 22.073,-18.847 24.587,-21.361 24.587,-42.647 25.451,-43.51 25.451,-44.094
BG on Signal Layer 2 "  " (solid, remove dead copper, pour order 676): 28.778,-42.469 28.321,-42.469 28.143,-42.291 28.143,-40.564 28.473,-40.234 36.728,-40.234 42.697,-34.265 45.034,-34.265 45.441,-34.671 45.441,-36.17 45.085,-36.525 43.866,-36.525 43.485,-36.144 42.85,-36.144 37.541,-41.453 29.794,-41.453
NetC8_2 on Signal Layer 2 "  " (solid, remove dead copper, pour order 678): 26.797,-43.282 25.679,-43.282 24.968,-42.57 24.968,-29.21 25.781,-28.397 26.746,-28.397 26.822,-28.473 26.492,-28.804 26.492,-41.758 27,-42.266 27,-43.078
NetC1_1 on Signal Layer 2 "  " (solid, remove dead copper, pour order 684): 1.803,-12.471 1.88,-12.395 11.938,-12.395 13.64,-14.097 13.64,-27.28 13.716,-27.356 13.945,-27.356 14.097,-27.203 14.097,-13.868 15.392,-12.573 18.669,-12.573 19.329,-13.233 19.329,-21.996 20.015,-22.682 21.717,-22.682 22.149,-23.114 22.149,-24.308 22.174,-24.333 22.174,-34.036 19.888,-36.322 2.438,-36.322 1.524,-35.408
NetC8_2 on Signal Layer 2 "  " (solid, remove dead copper, pour order 690): 11.074,-5.385 11.633,-4.826 33.401,-4.826 35.535,-6.96 35.535,-19.126 40.056,-23.647 40.056,-32.334 38.481,-33.909 26.645,-33.909 26.518,-34.036 25.984,-34.036 24.968,-33.02 24.968,-20.549 22.377,-17.958 21.514,-17.958 20.168,-16.612 20.168,-12.624 19.177,-11.633 11.849,-11.633 11.074,-10.858
NetC9_2 on Signal Layer 2 "  " (solid, remove dead copper, pour order 698): 37.567,-6.96 39.243,-5.283 54.915,-5.283 56.109,-6.477 56.109,-15.9 55.22,-16.789 55.22,-23.305 53.454,-25.07 45.872,-25.07 43.663,-22.86 41.656,-22.86 37.465,-18.669 37.465,-6.985 37.617,-6.833
VOUT on Signal Layer 2 "  " (solid, remove dead copper, pour order 710): 59.614,-14.529 66.472,-14.529 67.564,-15.621 67.564,-34.366 66.218,-35.712 55.423,-35.712 54.635,-34.925 54.635,-28.118 56.515,-26.238 56.515,-17.628
PGND on Signal Layer 2 "  " (solid, remove dead copper, pour order 720): 0.584,-2.896 0.584,-2.337 69.063,-2.337 69.063,-70.561 0.178,-70.561 0.178,-53.188
NetC1_1 on Bottom Layer "  " (solid, remove dead copper, pour order 686): 2.108,-12.395 2.184,-12.319 11.913,-12.319 13.614,-14.021 13.614,-26.873 13.919,-27.178 14.072,-27.178 14.072,-13.818 15.443,-12.446 18.567,-12.446 19.66,-13.538 19.66,-21.438 20.523,-22.301 21.539,-22.301 22.327,-23.089 22.327,-33.909 19.431,-36.805 2.489,-36.805 1.422,-35.738 1.422,-14.097
NetC8_2 on Bottom Layer "  " (solid, remove dead copper, pour order 694): 11.1,-5.486 11.811,-4.775 33.477,-4.775 35.636,-6.934 35.636,-19.126 40.081,-23.571 40.081,-32.258 38.456,-33.884 25.4,-33.884 23.216,-31.699 23.216,-18.999 20.269,-16.053 20.269,-12.624 19.279,-11.633 11.659,-11.633 11.074,-11.049 11.074,-5.537 11.151,-5.461
NetC9_2 on Bottom Layer "  " (solid, remove dead copper, pour order 702): 39.649,-5.055 56.21,-5.055 57.683,-6.528 57.683,-14.58 55.728,-16.535 55.728,-23.419 54.635,-24.511 43.713,-24.511 37.49,-18.288 37.49,-7.214
VOUT on Bottom Layer "  " (solid, remove dead copper, pour order 712): 59.436,-14.554 59.588,-14.402 66.421,-14.402 67.742,-15.723 67.742,-34.442 66.523,-35.662 55.702,-35.662 54.737,-34.696 54.737,-27.203 57.074,-24.867 57.074,-16.891 59.309,-14.656
PGND on Bottom Layer "  " (solid, remove dead copper, pour order 722): 0.508,-2.565 69.063,-2.565 69.063,-70.815 0.102,-70.815 0.102,-60.985
NetC1_1 on Signal Layer 1 "  " (solid, remove dead copper, pour order 682): 1.803,-12.421 1.829,-12.446 11.963,-12.446 13.64,-14.122 13.64,-27.28 13.741,-27.381 13.767,-27.356 13.945,-27.356 14.097,-27.203 14.097,-13.894 15.367,-12.624 18.694,-12.624 19.71,-13.64 19.71,-21.336 20.371,-21.996 21.996,-21.996 22.555,-22.555 22.555,-33.934 20.117,-36.373 2.438,-36.373 1.626,-35.56
NetC8_2 on Signal Layer 1 "  " (solid, remove dead copper, pour order 692): 11.049,-5.436 11.735,-4.75 33.452,-4.75 35.662,-6.96 35.662,-19.177 39.929,-23.444 39.929,-32.233 38.379,-33.782 25.4,-33.782 23.165,-31.547 23.165,-18.796 22.276,-17.907 21.641,-17.907 20.295,-16.561 20.295,-12.598 18.999,-11.303 11.963,-11.303 10.998,-10.338
NetC9_2 on Signal Layer 1 "  " (solid, remove dead copper, pour order 700): 39.548,-5.055 56.007,-5.055 57.658,-6.706 57.658,-14.656 55.677,-16.637 55.677,-23.698 53.645,-25.73 44.679,-25.73 37.338,-18.39 37.338,-7.264
VOUT on Signal Layer 1 "  " (solid, remove dead copper, pour order 714): 59.69,-14.427 59.868,-14.249 66.548,-14.249 67.361,-15.062 67.361,-34.95 66.548,-35.763 55.524,-35.763 54.813,-35.052 54.813,-27.508 57.048,-25.273 57.048,-17.196
PGND on Signal Layer 1 "  " (solid, remove dead copper, pour order 718): 0.914,-3.251 0.914,-2.565 70.028,-2.565 70.028,-70.333 -0.381,-70.333 -0.381,-62.535
no net on Bottom Solder "  " (hatched Horizontal grid 0.025 track 0.025, remove dead copper): 3.023,-14.046 3.785,-13.284 9.957,-13.284 11.811,-15.138 11.811,-28.092 12.929,-29.21 14.415,-29.21 15.494,-28.131 15.494,-23.47 16.408,-22.555 20.65,-22.555 21.387,-23.292 21.387,-33.147 18.212,-36.322 5.436,-36.322 2.845,-33.731 2.845,-14.427
no net on Bottom Solder "  " (hatched Horizontal grid 0.025 track 0.025, remove dead copper): 32.842,-5.334 34.798,-7.29 34.798,-20.015 38.989,-24.206 38.989,-31.928 37.984,-32.933 26.913,-32.933 24.181,-30.201 24.181,-18.136 21.285,-15.24 21.285,-11.557 20.422,-10.693 12.09,-10.693 11.633,-10.236 11.633,-6.02 12.319,-5.334
no net on Bottom Solder "  " (hatched Horizontal grid 0.025 track 0.025, remove dead copper): 38.354,-7.874 38.354,-7.62 40.437,-5.537 55.55,-5.537 56.896,-6.883 56.896,-13.792 54.813,-15.875 54.813,-23.012 53.848,-23.978 44.272,-23.978 37.922,-17.628 37.922,-8.001 38.303,-7.62
no net on Bottom Solder "  " (hatched Horizontal grid 0.025 track 0.025, remove dead copper): 59.182,-15.875 60.147,-14.91 64.973,-14.91 65.989,-15.926 65.989,-33.782 64.948,-34.823 56.921,-34.823 55.296,-33.198 55.296,-27.584 57.912,-24.968 57.912,-17.196 59.207,-15.9

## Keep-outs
Keep-Out Layer:
  the board outline again, w0.1

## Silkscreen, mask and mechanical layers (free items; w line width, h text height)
Top Overlay:
  circle w0.3: c6.68,-20.879 r2.8
  circle w0.3: c6.68,-53.67 r2.8
  circle w0.3: c62.173,-53.67 r2.8
  circle w0.3: c62.173,-20.879 r2.8
  lines w0.203: 10.617,-64.237 20.523,-64.237 ; 12.319,-67.183 12.319,-64.287 ; 13.97,-67.183 13.97,-62.052 ; 15.697,-67.234 15.697,-64.338 ; 16.84,-62.001 17.348,-62.001 17.348,-67.183 ; 18.872,-67.183 18.872,-64.287 ; 10.592,-67.234 20.625,-67.234 20.625,-62.001 10.719,-62.001 10.592,-62.001 10.592,-67.234
  text "TX41601" at 11.024,-7.925 h3.05
  text "DEMO V 1.0" at 11.455,-9.83 h1.91
  text "VIN" at 4.547,-15.641 h2.54
  text "VOUT" at 59.461,-15.875 h2.54
  text "GND" at 4.216,-59.284 h2.54
  text "GND" at 59.639,-59.608 h2.54
  text "EXT" at 18.11,-62.992 h1.14
  text "TOFF" at 14.427,-63.373 h1.14
  text "EN" at 11.557,-63.398 h1.14
  text "VCC" at 17.932,-63.957 h1.14
  text "VIN" at 18.376,-66.269 h0.76 r90
  text "VCC" at 15.113,-66.319 h0.76 r90
  text "VIN1" at 11.786,-66.345 h0.76 r90
  text "GND" at 16.789,-66.37 h0.76 r90
  text "GND" at 13.335,-66.421 h0.76 r90
  text "VOUT" at 19.914,-66.65 h0.76 r90
Bottom Solder:
  rectangle: 26.619,-49.936 32.893,-47.6
  lines w1.524: 6.985,-43.485 19.914,-43.485 ; 7.595,-48.692 28.423,-48.692 ; 14.808,-40.615 24.968,-40.615 ; 15.342,-38.379 55.143,-38.379 ; 31.437,-49.555 59.436,-49.555 ; 43.383,-46.634 60.122,-46.634 ; 44.806,-40.869 59.715,-40.869 ; 48.057,-43.561 61.925,-43.561 ; 48.946,-52.045 58.293,-52.045
Mechanical 1:
  lines w0.127: 1.956,-61.55 9.431,-61.55 9.431,-68.986 ; 1.981,-11.55 9.431,-11.55 9.431,-4.166 ; 59.436,-68.986 59.431,-68.986 59.431,-61.55 66.751,-61.55 ; 59.436,-4.089 59.436,-11.55 66.827,-11.55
